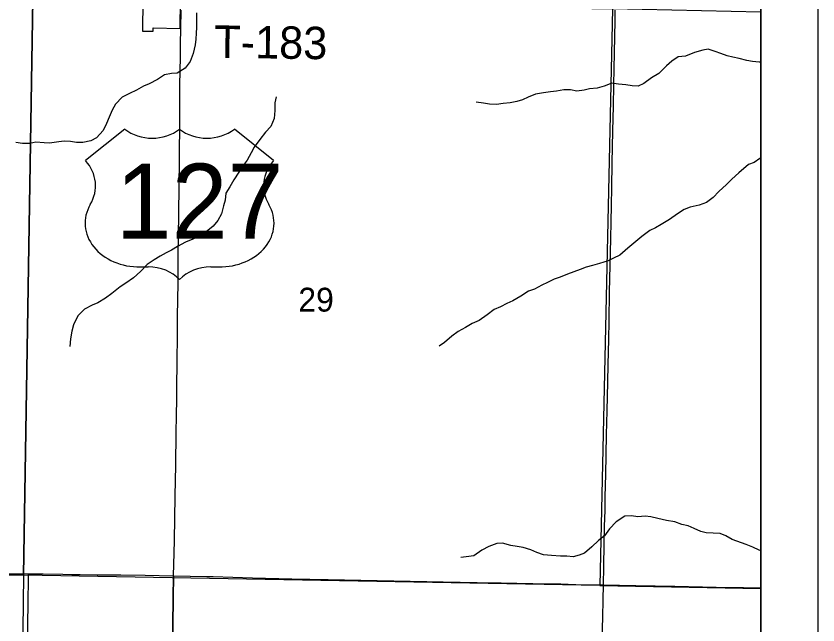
# Model space of a CAD drawing. Extents: x 0 to 34, y 0 to 22.
# Drawn here: x 7.593 to 9, y 17.342 to 18.41 of the extents above; entities that cross this region are included whole.
import ezdxf

# ---------------------------------------------------------------- set-up
doc = ezdxf.new("R2010")
doc.units = 0
for name, color, linetype in [('GM_X_County_Road', 7, 'Continuous'), ('GM_X_County_Text', 7, 'Continuous'), ('GM_X_Minor_River', 7, 'Continuous'), ('GM_X_Rail_Line_Text', 7, 'Continuous'), ('GM_X_Section', 7, 'Continuous'), ('GM_X_Section_Text', 7, 'Continuous'), ('GM_X_State_Route', 7, 'Continuous'), ('GM_X_Township_Road_Text', 7, 'Continuous'), ('GM_X_US_Location', 7, 'Continuous'), ('GM_X_US_Route', 7, 'Continuous'), ('GM_X_US_Shield', 7, 'Continuous'), ('SH_Cut_Line', 7, 'Continuous'), ('SH_Data', 7, 'Continuous')]:
    doc.layers.add(name, color=color, linetype=linetype)

msp = doc.modelspace()

# ---------------------------------------------------------------- linework, layer by layer
at = {"layer": 'GM_X_County_Road'}
for points in [[(8.6238, 17.4124), (8.6242, 17.4444), (8.625, 17.4842), (8.6255, 17.5153), (8.6263, 17.5432), (8.6268, 17.567), (8.6275, 17.606), (8.6291, 17.6756), (8.6299, 17.7179), (8.6311, 17.7683), (8.6317, 17.7993), (8.6327, 17.8429), (8.6334, 17.8758), (8.6344, 17.9261), (8.6363, 18.02), (8.6369, 18.0492), (8.6375, 18.0778), (8.6381, 18.1095), (8.639, 18.1524), (8.6401, 18.209), (8.6409, 18.2519), (8.6418, 18.2898), (8.643, 18.3457), (8.6441, 18.4023), (8.6441, 18.4208)], [(7.6125, 17.293), (7.614, 17.385), (7.6143, 17.4199), (7.6144, 17.432)], [(8.6214, 17.3207), (8.6223, 17.3549), (8.6233, 17.3872), (8.6237, 17.4115), (8.6238, 17.4124)]]:
    msp.add_lwpolyline(points, dxfattribs=at)
at = {"layer": 'GM_X_County_Text'}
msp.add_lwpolyline([(8.9, 16.3981), (8.9, 20.9)], dxfattribs=at)
at = {"layer": 'GM_X_Minor_River'}
for points in [[(7.9093, 18.4158), (7.9094, 18.4033), (7.9092, 18.3904), (7.9086, 18.3801), (7.908, 18.3695), (7.9071, 18.3597), (7.9034, 18.3446), (7.8982, 18.3303), (7.8892, 18.319), (7.8754, 18.3102), (7.8655, 18.3096), (7.853, 18.3072), (7.841, 18.2987), (7.8261, 18.2911), (7.8166, 18.2875), (7.8039, 18.2805), (7.7917, 18.2743), (7.779, 18.2677), (7.767, 18.2554), (7.7615, 18.2449), (7.7563, 18.2329), (7.7516, 18.222), (7.7456, 18.2092), (7.7336, 18.1965), (7.7237, 18.1914), (7.7096, 18.1883), (7.699, 18.1885), (7.6884, 18.1902), (7.6774, 18.1908), (7.6679, 18.1898), (7.6516, 18.1875), (7.6421, 18.1877), (7.6277, 18.1891), (7.617, 18.1866), (7.6038, 18.1869), (7.5924, 18.1883)], [(8.9, 18.3291), (8.8966, 18.3294), (8.8852, 18.3304), (8.8754, 18.3325), (8.8618, 18.3358), (8.8505, 18.3379), (8.8407, 18.3407), (8.8294, 18.3444), (8.8196, 18.3483), (8.8072, 18.352), (8.7977, 18.3503), (8.7835, 18.3464), (8.7675, 18.3399), (8.7546, 18.3386), (8.7438, 18.3312), (8.7342, 18.3231), (8.721, 18.3093), (8.708, 18.3016), (8.6945, 18.292), (8.6842, 18.2872), (8.674, 18.2878), (8.6626, 18.2895), (8.6498, 18.2909), (8.6384, 18.2927), (8.6247, 18.2873), (8.6128, 18.2837), (8.5992, 18.2828), (8.5896, 18.28), (8.5767, 18.2787), (8.5657, 18.2808), (8.554, 18.281), (8.5411, 18.2783), (8.5308, 18.2773), (8.5182, 18.2753), (8.5042, 18.2733), (8.4912, 18.2678), (8.4812, 18.2631), (8.4717, 18.2606), (8.4599, 18.2582), (8.4473, 18.2566), (8.4356, 18.2553), (8.4234, 18.2559), (8.4132, 18.2572), (8.4004, 18.259)], [(8.0494, 18.2685), (8.0469, 18.2583), (8.0467, 18.2443), (8.0456, 18.2303), (8.0401, 18.2163), (8.0304, 18.2067), (8.0207, 18.1936), (8.0105, 18.1801), (8.0054, 18.1703), (7.9983, 18.1576), (7.9913, 18.1479), (7.9749, 18.1231), (7.9679, 18.1108), (7.9608, 18.0995), (7.9594, 18.0874), (7.957, 18.0772), (7.9533, 18.0632), (7.947, 18.0516), (7.9388, 18.0415), (7.9261, 18.0315), (7.9135, 18.0249), (7.9028, 18.0191), (7.8898, 18.0136), (7.8763, 18.0063), (7.8656, 17.9997), (7.856, 17.995), (7.8457, 17.9891), (7.8353, 17.9828), (7.823, 17.9747), (7.811, 17.9621), (7.7987, 17.9513), (7.7856, 17.9417), (7.7756, 17.9351), (7.761, 17.9236), (7.7494, 17.9151), (7.736, 17.9074), (7.7261, 17.903), (7.7127, 17.8961), (7.7014, 17.8842), (7.6936, 17.8688), (7.6907, 17.8578), (7.6882, 17.8438), (7.6868, 17.8306)], [(8.9, 18.1625), (8.8979, 18.1605), (8.8883, 18.1535), (8.878, 18.1499), (8.8614, 18.1351), (8.849, 18.1239), (8.8394, 18.115), (8.8262, 18.1024), (8.8158, 18.0919), (8.8042, 18.0831), (8.7916, 18.0788), (8.7756, 18.0749), (8.7653, 18.0709), (8.7534, 18.0636), (8.7392, 18.0536), (8.7246, 18.0448), (8.7147, 18.0389), (8.7051, 18.0338), (8.6908, 18.0238), (8.6662, 18.0031), (8.6523, 17.9908), (8.6412, 17.9853), (8.6316, 17.9806), (8.6164, 17.976), (8.6045, 17.9728), (8.5935, 17.9696), (8.5824, 17.9656), (8.5717, 17.9613), (8.5606, 17.9573), (8.5473, 17.9523), (8.5373, 17.9487), (8.5255, 17.9428), (8.5155, 17.9381), (8.5025, 17.9311), (8.4922, 17.9275), (8.4787, 17.9191), (8.4645, 17.9106), (8.4538, 17.9059), (8.4427, 17.9004), (8.432, 17.8953), (8.4193, 17.8861), (8.4055, 17.8761), (8.3929, 17.8707), (8.3813, 17.8637), (8.3683, 17.8568), (8.3572, 17.8486), (8.3448, 17.8375), (8.3352, 17.8312)], [(8.9, 17.4721), (8.8967, 17.4733), (8.8858, 17.4784), (8.8742, 17.4832), (8.8493, 17.492), (8.8381, 17.4987), (8.8283, 17.5027), (8.8161, 17.5033), (8.804, 17.5035), (8.7942, 17.5064), (8.7826, 17.5115), (8.772, 17.5159), (8.7611, 17.5184), (8.7486, 17.5228), (8.7343, 17.5253), (8.7188, 17.5291), (8.7067, 17.5316), (8.6969, 17.5329), (8.6836, 17.532), (8.673, 17.5337), (8.6609, 17.5332), (8.6459, 17.5233), (8.6343, 17.511), (8.6253, 17.4983), (8.6149, 17.4901), (8.6033, 17.4793), (8.5902, 17.4682), (8.5807, 17.4646), (8.5704, 17.4614), (8.5594, 17.4628), (8.548, 17.4626), (8.5325, 17.464), (8.5185, 17.4654), (8.5064, 17.4695), (8.4959, 17.4742), (8.4827, 17.4779), (8.4721, 17.4796), (8.4608, 17.4817), (8.4465, 17.4854), (8.4366, 17.4852), (8.4225, 17.4798), (8.4102, 17.4736), (8.396, 17.4637)], [(8.396, 17.4637), (8.3827, 17.4616), (8.3732, 17.4607)]]:
    msp.add_lwpolyline(points, dxfattribs=at)
at = {"layer": 'GM_X_Rail_Line_Text'}
msp.add_lwpolyline([(8.9, 17.4062), (8.9, 18.4172), (8.6393, 18.4229), (8.6173, 17.4112)], close=True, dxfattribs=at)
at = {"layer": 'GM_X_Section'}
for points in [[(6.6853, 18.443), (7.6223, 18.4397), (7.606, 17.4298), (6.6654, 17.4415)], [(7.6223, 18.4397), (8.6393, 18.4229), (8.6173, 17.4112), (7.606, 17.4298)], [(6.6654, 17.4415), (7.606, 17.4298), (7.5935, 16.4205), (7.5749, 16.4209), (6.6455, 16.4378)]]:
    msp.add_lwpolyline(points, close=True, dxfattribs=at)
at = {"layer": 'GM_X_State_Route'}
msp.add_line((7.8817, 18.3877), (7.8822, 18.4203), dxfattribs=at)
for points in [[(7.8783, 18.0614), (7.8783, 18.0644), (7.8795, 18.1576), (7.8796, 18.1844), (7.8799, 18.2037), (7.8802, 18.249), (7.8803, 18.2589), (7.8804, 18.2876), (7.8807, 18.3155), (7.881, 18.337), (7.8814, 18.3653), (7.8816, 18.3836), (7.8817, 18.3877)], [(7.8774, 17.9815), (7.8774, 17.9904), (7.8783, 18.0614)], [(7.8691, 17.4286), (7.87, 17.4685), (7.8705, 17.4902), (7.8719, 17.5683), (7.8729, 17.6223), (7.8738, 17.6789), (7.8742, 17.7097), (7.8746, 17.7384), (7.8749, 17.7628), (7.8754, 17.7995), (7.8759, 17.8544), (7.8762, 17.8832), (7.8765, 17.9132), (7.877, 17.9419), (7.8774, 17.9815)], [(6.6685, 17.4383), (6.6918, 17.4381), (6.8106, 17.4375), (6.8603, 17.437), (6.9374, 17.4364), (6.9859, 17.4361), (7.0344, 17.4358), (7.0797, 17.4354), (7.14, 17.435), (7.2022, 17.4344), (7.2339, 17.4342), (7.2995, 17.434), (7.3856, 17.4337), (7.4123, 17.4336), (7.4807, 17.4331), (7.5682, 17.4324), (7.6144, 17.432)], [(7.6144, 17.432), (7.6404, 17.4318), (7.6747, 17.4314), (7.6908, 17.4309), (7.7051, 17.4306), (7.7353, 17.4303), (7.7539, 17.4301), (7.7692, 17.43)], [(7.7692, 17.43), (7.7764, 17.4299), (7.8195, 17.4296), (7.8691, 17.4286)], [(7.8691, 17.4286), (7.8686, 17.3899), (7.868, 17.3414), (7.8676, 17.3078), (7.8674, 17.2718), (7.867, 17.2457), (7.8652, 17.1201), (7.8647, 17.0722), (7.8633, 16.9641), (7.863, 16.9261), (7.8624, 16.8826), (7.8616, 16.8211), (7.8612, 16.7838), (7.8609, 16.7682), (7.8605, 16.7285), (7.8601, 16.703), (7.8599, 16.6806), (7.8597, 16.6663)]]:
    msp.add_lwpolyline(points, dxfattribs=at)
at = {"layer": 'GM_X_US_Route'}
for p, q in [((7.8817, 18.3877), (7.8822, 18.4203)), ((7.8691, 17.4286), (7.9275, 17.4274))]:
    msp.add_line(p, q, dxfattribs=at)
for points in [[(7.815, 18.438), (7.8144, 18.3839), (7.8334, 18.3836), (7.8334, 18.3893), (7.8808, 18.3885), (7.8814, 18.4385)], [(7.8783, 18.0614), (7.8783, 18.0644), (7.8795, 18.1576), (7.8796, 18.1844), (7.8799, 18.2037), (7.8802, 18.249), (7.8803, 18.2589), (7.8804, 18.2876), (7.8807, 18.3155), (7.881, 18.337), (7.8814, 18.3653), (7.8816, 18.3836), (7.8817, 18.3877)], [(7.8774, 17.9815), (7.8774, 17.9904), (7.8783, 18.0614)], [(7.8691, 17.4286), (7.87, 17.4685), (7.8705, 17.4902), (7.8719, 17.5683), (7.8729, 17.6223), (7.8738, 17.6789), (7.8742, 17.7097), (7.8746, 17.7384), (7.8749, 17.7628), (7.8754, 17.7995), (7.8759, 17.8544), (7.8762, 17.8832), (7.8765, 17.9132), (7.877, 17.9419), (7.8774, 17.9815)], [(6.6685, 17.4383), (6.6918, 17.4381), (6.8106, 17.4375), (6.8603, 17.437), (6.9374, 17.4364), (6.9859, 17.4361), (7.0344, 17.4358), (7.0797, 17.4354), (7.14, 17.435), (7.2022, 17.4344), (7.2339, 17.4342), (7.2995, 17.434), (7.3856, 17.4337), (7.4123, 17.4336), (7.4807, 17.4331), (7.5682, 17.4324), (7.6144, 17.432)], [(7.6144, 17.432), (7.6404, 17.4318), (7.6747, 17.4314), (7.6908, 17.4309), (7.7051, 17.4306), (7.7353, 17.4303), (7.7539, 17.4301), (7.7692, 17.43)], [(7.7692, 17.43), (7.7764, 17.4299), (7.8195, 17.4296), (7.8691, 17.4286)], [(7.8597, 16.6663), (7.8599, 16.6806), (7.8601, 16.703), (7.8605, 16.7285), (7.8609, 16.7682), (7.8612, 16.7838), (7.8616, 16.8211), (7.8624, 16.8826), (7.863, 16.9261), (7.8633, 16.9641), (7.8647, 17.0722), (7.8652, 17.1201), (7.867, 17.2457), (7.8674, 17.2718), (7.8676, 17.3078), (7.868, 17.3414), (7.8686, 17.3899), (7.8691, 17.4286)], [(7.9275, 17.4274), (7.9386, 17.4271), (8.0074, 17.4251), (8.0764, 17.4233), (8.1404, 17.4221), (8.1976, 17.4209), (8.3424, 17.4181), (8.4021, 17.4169), (8.4438, 17.4161), (8.4997, 17.415), (8.5488, 17.4141), (8.5749, 17.4132), (8.6238, 17.4124), (8.6806, 17.4114), (8.749, 17.4101), (8.8211, 17.4086), (8.8696, 17.4079), (8.9, 17.4072)]]:
    msp.add_lwpolyline(points, dxfattribs=at)
at = {"layer": 'GM_X_US_Shield'}
for p, q in [((7.7835, 18.2118), (7.7148, 18.1569)), ((8.0444, 18.1569), (7.9758, 18.2118)), ((7.811, 17.9701), (7.8247, 17.9701)), ((7.9346, 17.9701), (7.9483, 17.9701))]:
    msp.add_line(p, q, dxfattribs=at)
for centre, major_axis, start_param, end_param in [((7.8316, 18.251), (-0.0687, 0), 0.795399, 2.346194), ((7.9277, 18.251), (-0.0687, 0), 0.795399, 2.346194), ((7.6361, 18.1127), (0.0961, 0), 5.838949, 6.894067), ((8.1232, 18.1127), (-0.0961, 0), 5.672304, 6.727422), ((7.8099, 18.047), (0.0961, 0), 2.702327, 4.723529), ((7.9494, 18.047), (-0.0961, 0), 1.559657, 3.580859), ((7.8247, 17.9152), (-0.0687, 0), 3.785094, 4.712389), ((7.9346, 17.9152), (-0.0687, 0), 4.712389, 5.639684)]:
    msp.add_ellipse(centre, major_axis=major_axis, ratio=0.8, start_param=start_param, end_param=end_param, dxfattribs=at)
at = {"layer": 'SH_Cut_Line'}
msp.add_lwpolyline([(8.9, 16.3981), (8.9, 20.9)], dxfattribs=at)
at = {"layer": 'SH_Data'}
for p, q in [((9, 21), (9, 14)), ((8.9, 20.9), (8.9, 14.1))]:
    msp.add_line(p, q, dxfattribs=at)

# ---------------------------------------------------------------- texts
at = {"layer": 'GM_X_Section_Text'}
msp.add_text('29', height=0.04186, rotation=0, dxfattribs=at).set_placement((8.0881, 17.8918))
at = {"layer": 'GM_X_Township_Road_Text'}
msp.add_text('T-183', height=0.05682, rotation=359.1779, dxfattribs=at).set_placement((7.9401, 18.3372))
at = {"layer": 'GM_X_US_Location'}
for s, p in [('0', (7.8797, 18.0853)), ('/', (7.8798, 18.0853))]:
    msp.add_text(s, height=0.000189, dxfattribs=at).set_placement(p)
msp.add_text('127', height=0.000189, rotation=0, dxfattribs=at).set_placement((7.8215, 18.0461))
at = {"layer": 'GM_X_US_Shield'}
msp.add_text('127', height=0.13184, dxfattribs=at).set_placement((7.7678, 18.0195))

doc.saveas('drawing.dxf')
